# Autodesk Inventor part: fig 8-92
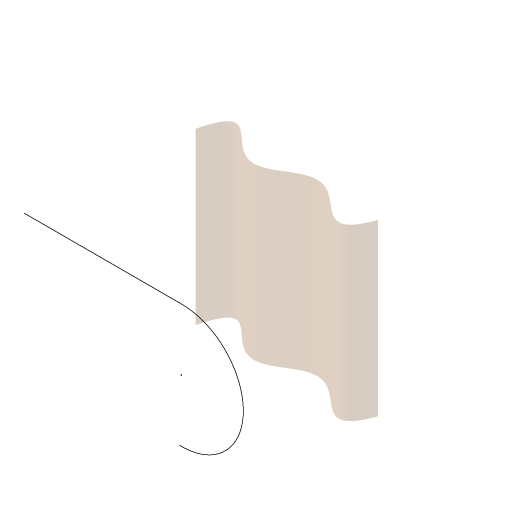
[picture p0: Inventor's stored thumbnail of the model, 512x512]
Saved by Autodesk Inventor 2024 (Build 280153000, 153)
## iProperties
Shininess: 64.0
Length Units: 11269
Angle Units: 11279
Time Units: 11290
Mass Units: 11283
Length Display Precision: 3
Angle Display Precision: 2
Compacted: True
Part Number: fig 8-92
Document SubType Name: Modeling
Created: 2003-08
Designer: Owner
Manufacturer: Standard
Standards Organization: Custom
Density: 1 g/cm^3
Material: Generic
Appearance: Default
Density: 0.0
Volumn: 0.0
Area: 0.0
PropertySet Name: Model Information
Control State: 0
Master: False
Checked Out: False
Author: Owner
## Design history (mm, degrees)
sketch "Sketch1"
  geometry: 7 further points
  constraints: 7 other
  dimensions: "d0" = 80 horizontal distance of point (40, 1.742) point (-40, -4.065); "d1" = 40 horizontal distance of point (0, 0) point (-40, -4.065)
extrude_surface "ExtrusionSrf1" sketch "Sketch1" dims "d2" = 80, "d3" = 0
sketch "Sketch2"
  geometry: L1 (40, 0)-(40, -40) reference; L2 (-40, 0)-(-40, -40) reference; 7 further points
  constraints: 2 point on line, 7 other
extrude_surface "ExtrusionSrf2" sketch "Sketch2" dims "d4" = 80, "d5" = 0
workplane "Work Plane1"
sketch "Sketch4"
  geometry: L1 (70.027, 16.004)-(-4, 16.004); A1 r 29.004 centre (-4, -13) between (-4, 16.004) and (-2.981, -41.986)
  constraints: 2 end point, 2 point on circle, 1 centre point, 1 horizontal, 1 tangent
body "Srf1"
body "Srf2"
other parameters: "d6" = -54.75
